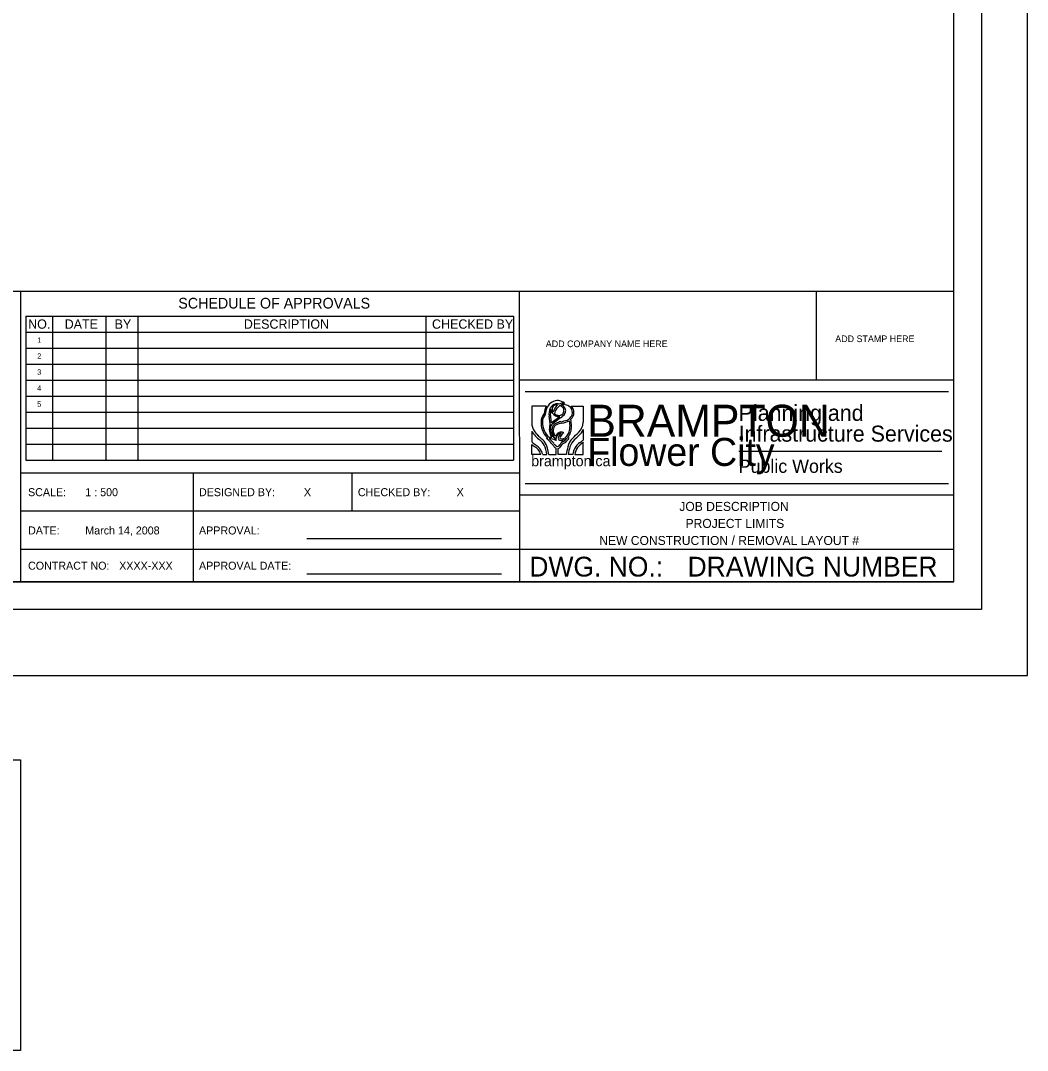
# Model space of a CAD drawing. Extents: x 602909 to 603631, y 4846273 to 4846729.
# Drawn here: x 603194.8 to 603377, y 4846272.8 to 4846459.2 of the extents above; entities that cross this region are included whole.
import ezdxf

# ---------------------------------------------------------------- set-up
doc = ezdxf.new("R2010")
doc.units = 0
for name, color, linetype in [('-PRINT FULLSIZE', 7, 'Continuous'), ('-PRINT HALFSIZE', 7, 'Continuous'), ('ENG_BORDER', 7, 'Continuous'), ('ENG_LOGO', 7, 'Continuous'), ('ENG_TITLEBLOCK', 7, 'Continuous'), ('ENG_TX_LOGO', 7, 'Continuous'), ('ENG_TX_TITLEBLOCK', 7, 'Continuous'), ('ENG_WK_MISC-1', 7, 'Continuous'), ('SL - Border Text', 7, 'Continuous')]:
    doc.layers.add(name, color=color, linetype=linetype)

# ---------------------------------------------------------------- blocks, each defined once
blk = doc.blocks.new('PIS-PW TITLE-H')
at = {"layer": 'ENG_LOGO'}
for p, q in [((-75.42, 14.45), (-78.15, 14.45)), ((-78.15, 14.45), (-78.15, 11.26)), ((-70.72, 14.45), (-68.47, 14.45)), ((-68.47, 14.45), (-68.47, 11.45)), ((-74.69, 11.23), (-74.85, 12.58)), ((-74.43, 11.34), (-74.65, 13.06)), ((-72.89, 12.5), (-74.43, 11.34)), ((-72.76, 12.26), (-74.31, 11.1)), ((-78.15, 9.79), (-78.15, 7.81)), ((-68.47, 10.08), (-68.47, 8.17)), ((-74.92, 8.64), (-74.39, 8.64)), ((-73.76, 8.31), (-73.76, 8.45)), ((-72.07, 7.93), (-71.51, 8.46)), ((-78.15, 5.39), (-78.15, 7.29)), ((-73.55, 5.39), (-73.55, 6.62)), ((-73.17, 5.39), (-73.17, 6.56)), ((-68.47, 5.39), (-68.47, 7.65)), ((-76.45, 5.39), (-78.15, 5.39)), ((-76.06, 5.39), (-75.33, 5.39)), ((-74.96, 5.39), (-73.55, 5.39)), ((-71.67, 5.39), (-73.17, 5.39)), ((-70.41, 5.39), (-71.29, 5.39)), ((-70.05, 5.39), (-68.47, 5.39))]:
    blk.add_line(p, q, dxfattribs=at)
for centre, major_axis, start_param, end_param in [((-73.32, 12.77), (0, 2.75), 5.678233, 7.807497), ((-73.93, 13.08), (0, 2.24), 0.915828, 1.568717), ((-73.37, 13.09), (0, -1.84), 3.318986, 4.976585), ((-73.42, 13.22), (0, 1.47), 1.119551, 1.674398), ((-73.07, 13.94), (0, -1.75), 4.758696, 4.974719), ((-73.69, 13.89), (0, 0.753), 1.423327, 2.376918), ((-73.81, 14), (0, 0.606), 0.666047, 1.576027), ((-72, 12.52), (0, 2.67), 0.628774, 1.255965), ((-73.5, 13.33), (0, 1.36), 6.118882, 6.855525), ((-71.91, 12.4), (0, 2.47), 0.484278, 1.276713), ((-73.45, 13.49), (0, 1.43), 5.937042, 6.443816), ((-72.17, 12.32), (0, 2.72), 6.209925, 6.677582), ((-73.16, 13.3), (0, 1.33), 5.514665, 6.02559), ((-72.16, 12.72), (0, 2.07), 6.104016, 6.552384), ((-72.88, 13.34), (0, 1.4), 5.100192, 6.058655), ((-72.72, 13.61), (0, 0.767), 4.934552, 5.720905), ((-72.91, 13.71), (0, -0.969), 0.785512, 1.640949), ((-72.69, 13.68), (0, 1.09), 4.195874, 4.894963), ((-72.33, 11.8), (0, 3), 5.705811, 6.088794), ((-71.57, 13.27), (0, 1.28), 4.747453, 5.681752), ((-71.24, 13.43), (0, 1.19), 4.858966, 5.733736), ((-72.43, 13.38), (0, -2.61), 1.316711, 1.656268), ((-74.49, 11.45), (0, 2.27), 0.764321, 1.571722), ((-74.55, 11.5), (0, 1.9), 0.74139, 1.563754), ((-75.01, 12.56), (0, -0.186), 1.717889, 1.834992), ((-73.96, 13.66), (0, -0.65), 4.989814, 5.515803), ((-73, 14.66), (0, -2.16), 5.455385, 6.346676), ((-73.1, 14.2), (0, -1.44), 5.558935, 6.198642), ((-73, 14.01), (0, -1.26), 6.098575, 6.969537), ((-73.81, 14.79), (0, -2.82), 0.460861, 0.945922), ((-74.45, 24.58), (0, -13.19), 0.161819, 0.267812), ((-74.01, 21.47), (0, -10.34), 0.177455, 0.344982), ((-72.14, 13.9), (0, -2.16), 0.344201, 0.831804), ((-73.76, 10.77), (0, 3.34), 4.273394, 5.005808), ((-72.01, 13.79), (0, -2.29), 0.654188, 1.084874), ((-74.63, 10.73), (0, -4.7), 1.565289, 1.83996), ((-71.33, 13.22), (0, 0.997), 3.823835, 4.807307), ((-76.01, 11.44), (0, -2.56), 4.785712, 5.370532), ((-75.36, 11.97), (0, -3.98), 5.292666, 5.605077), ((-73.65, 13.61), (0, -6.12), 5.369755, 5.566262), ((-74.17, 11.24), (0, 2.66), 1.493845, 2.002346), ((-73.58, 11.27), (0, -3.33), 5.06368, 5.674398), ((-73.24, 11.46), (0, 3.46), 1.555738, 2.522651), ((-72.88, 10.15), (0, 2.35), 1.184297, 2.265825), ((-74.99, 11.18), (0, 0.371), 4.32589, 4.859481), ((-72.5, 10.29), (0, -2.55), 4.68622, 4.981796), ((-73.83, 10.33), (0, 0.964), 0.63706, 1.540523), ((-72.74, 10.03), (0, 1.93), 1.258524, 1.853874), ((-73.29, 9.91), (0, 1.38), 0.28455, 1.028854), ((-73.1, 9.94), (0, 1.21), 1.326911, 2.090694), ((-73.34, 10.1), (0, 0.888), 0.179588, 1.425103), ((-72.62, 8.16), (0, 1.44), 5.87892, 7.368381), ((-71.39, 4.29), (0, 7.44), 0.207106, 0.364997), ((-71.81, 5.89), (0, 5.46), 0.147367, 0.372097), ((-72.98, 10.56), (0, -2.73), 0.78097, 1.623824), ((-71.01, 11.91), (0, -3.07), 0.712478, 1.421371), ((-71.69, 12.5), (0, -4.55), 0.682687, 1.010528), ((-73.45, 15.04), (0, -9.15), 5.623762, 5.757196), ((-74.17, 13.11), (0, -5.77), 5.537119, 5.75381), ((-11.92, 112.2), (0, -129.21), 5.63745, 5.644913), ((-78.53, 4.94), (0, 3.93), 5.320654, 5.659535), ((-77.29, 6.41), (0, 2.29), 5.416876, 5.78378), ((-77.88, 5.61), (0, 3.35), 5.018027, 5.462353), ((-74.77, 7.29), (0, 1.34), 0.365522, 0.597805), ((-77.01, 4.73), (0, 4.14), 5.439641, 5.800947), ((-74.75, 5.22), (0, 3.14), 5.823202, 6.334077), ((-77.76, 3.17), (0, 6.23), 5.482733, 5.697338), ((-72.53, 10.38), (0, -2.54), 5.019488, 5.665896), ((-72.42, 10.14), (0, -2.33), 4.995413, 5.526463), ((-72.63, 10.06), (0, -1.76), 5.131028, 5.477302), ((-72.6, 8.21), (0, -1.19), 3.173377, 4.865507), ((-72.84, 8.49), (0, 0.39), 1.287529, 2.899642), ((-72.16, 8.3), (0, 1.23), 0.477744, 1.324571), ((-72.57, 9.14), (0, -1.11), 5.896411, 6.466099), ((-72.62, 8.59), (0, 0.276), 0.693494, 2.795441), ((-71.13, 7.42), (0, 2.4), 0.532188, 0.957727), ((-72.28, 7.12), (0, 0.637), 0.214109, 1.153309), ((-72.57, 10.32), (0, -2), 6.206413, 6.519617), ((-73.45, 12.88), (0, -4.98), 0.25264, 0.48256), ((-73.31, 10.42), (0, -2.89), 0.390063, 0.537232), ((-73.45, 10.87), (0, -3.72), 0.408149, 0.566756), ((-72.98, 10.64), (0, -2.45), 0.401305, 1.020747), ((-74.54, 11.95), (0, -5.35), 0.664019, 0.865631), ((-71.66, 7.54), (0, 1.13), 5.695616, 5.978543), ((-69.07, 6.19), (0, 2.82), 0.6523, 1.336939), ((-68.18, 5.39), (0, 3.66), 0.690534, 1.157714), ((-96.81, 48.11), (0, -50.61), 0.669806, 0.705808), ((-82.82, 29.47), (0, -26.1), 0.619451, 0.667551), ((-75.9, 20.01), (0, -14.8), 0.573803, 0.643743), ((-74.61, 13.52), (0, -7.52), 5.687848, 5.809574), ((-78.43, 4.59), (0, 2.5), 5.497917, 5.817483), ((-79.56, 2.67), (0, 5.21), 5.540505, 5.738863), ((-78.51, 4.55), (0, 2.6), 5.039091, 5.480629), ((-78.45, 4.47), (0, 3), 5.021624, 5.458474), ((-78.36, 5.18), (0, 3.62), 4.76812, 5.296774), ((-78.91, 4.92), (0, 4.75), 4.811691, 5.079969), ((-85.55, -5.35), (0, 18.48), 5.441321, 5.480214), ((-72.71, 8.74), (0, -2), 5.382989, 5.704264), ((-73.35, 7.64), (0, -1.05), 5.423199, 6.055208), ((-73.3, 7.54), (0, -0.612), 5.581796, 6.941571), ((-73.56, 7.96), (0, -1.47), 0.32402, 1.048968), ((-75.34, 9.63), (0, -3.81), 0.828888, 0.938456), ((-71.86, 6.52), (0, 1.03), 0.422403, 0.821661), ((-65.77, 4.42), (0, 7.11), 1.223572, 1.434629), ((-61.41, 3.3), (0, 11.98), 1.268607, 1.395258), ((-68.35, 5.26), (0, 2.47), 0.824174, 1.519908), ((-67.53, 4.86), (0, 3.06), 0.923116, 1.39853), ((-68.28, 5.34), (0, 2.48), 0.445246, 0.869293), ((-67.08, 3.92), (0, 4.08), 0.417687, 0.818457)]:
    blk.add_ellipse(centre, major_axis=major_axis, ratio=0.837209, start_param=start_param, end_param=end_param, dxfattribs=at)
at = {"layer": 'ENG_TITLEBLOCK'}
for p, q in [((-79.4, 17.2), (0, 17.2)), ((-39.34, 6.03), (-1.27, 6.04)), ((-79.4, 0), (0, 0))]:
    blk.add_line(p, q, dxfattribs=at)
at = {"layer": 'ENG_TX_LOGO'}
blk.add_text('brampton.ca', height=2, rotation=0.002, dxfattribs=at).set_placement((-78.24, 3.21))
at = {"layer": 'ENG_TX_TITLEBLOCK'}
for s, height, p in [('BRAMPTON', 6, (-67.72, 8.74)), ('Planning and', 3, (-39.34, 11.71)), ('Infrastructure Services', 3, (-39.34, 7.82)), ('Flower City', 5.25, (-67.72, 3.27)), ('Public Works', 2.5, (-39.34, 1.97))]:
    blk.add_text(s, height=height, rotation=0.0021, dxfattribs=at).set_placement(p)

msp = doc.modelspace()

# ---------------------------------------------------------------- linework, layer by layer
at = {"layer": '-PRINT FULLSIZE'}
msp.add_lwpolyline([(602930, 4846340.65), (603377.03, 4846340.65), (603377.03, 4846645.65), (602930, 4846645.65)], close=True, dxfattribs=at)
at = {"layer": '-PRINT HALFSIZE'}
msp.add_lwpolyline([(602959.8, 4846631.64), (603368.72, 4846631.64), (603368.72, 4846352.64), (602959.8, 4846352.64)], close=True, dxfattribs=at)
at = {"layer": 'ENG_BORDER'}
for p, q in [((603363.72, 4846357.64), (603363.72, 4846626.85)), ((602977.52, 4846410.23), (603363.74, 4846410.23)), ((603194.76, 4846410.25), (603194.76, 4846357.64)), ((603285.12, 4846357.64), (603285.08, 4846410.25)), ((603338.86, 4846394.19), (603338.86, 4846410.23)), ((603285.09, 4846394.19), (603363.72, 4846394.19)), ((603285.11, 4846377.32), (603194.76, 4846377.32)), ((603226.09, 4846357.72), (603226.09, 4846377.32)), ((603254.8, 4846370.39), (603254.8, 4846377.32)), ((603285.23, 4846373.35), (603363.75, 4846373.35)), ((603285.14, 4846370.39), (603194.76, 4846370.39)), ((603363.66, 4846363.45), (603194.76, 4846363.45)), ((603363.72, 4846357.64), (602977.52, 4846357.64))]:
    msp.add_line(p, q, dxfattribs=at)
for points in [[(602977.52, 4846357.64), (603363.72, 4846357.64), (603363.72, 4846626.64), (602977.52, 4846626.64)], [(603054.8, 4846325.39), (603194.76, 4846325.39), (603194.76, 4846272.8), (603054.8, 4846272.8)]]:
    msp.add_lwpolyline(points, close=True, dxfattribs=at)
at = {"layer": 'ENG_TX_TITLEBLOCK'}
for points in [[(603246.57, 4846365.47), (603281.85, 4846365.47)], [(603246.57, 4846359.1), (603281.85, 4846359.1)]]:
    msp.add_lwpolyline(points, dxfattribs=at)
at = {"layer": 'SL - Border Text'}
for p, q in [((603195.73, 4846405.73), (603195.73, 4846379.66)), ((603195.73, 4846405.73), (603284.02, 4846405.73)), ((603200.56, 4846405.73), (603200.56, 4846379.66)), ((603210.21, 4846405.73), (603210.21, 4846379.66)), ((603216, 4846405.73), (603216, 4846379.66)), ((603268.14, 4846405.73), (603268.14, 4846379.66)), ((603284.02, 4846405.73), (603284.02, 4846379.66)), ((603195.73, 4846402.84), (603284.02, 4846402.84)), ((603195.73, 4846399.94), (603284.02, 4846399.94)), ((603195.73, 4846397.04), (603284.02, 4846397.04)), ((603195.73, 4846394.15), (603284.02, 4846394.15)), ((603195.73, 4846391.25), (603284.02, 4846391.25)), ((603195.73, 4846388.35), (603284.02, 4846388.35)), ((603195.73, 4846385.46), (603284.02, 4846385.46)), ((603195.73, 4846382.56), (603284.02, 4846382.56)), ((603195.73, 4846379.66), (603284.02, 4846379.66))]:
    msp.add_line(p, q, dxfattribs=at)

# ---------------------------------------------------------------- block references
at = {"layer": 'ENG_WK_MISC-1', "xscale": 0.9654884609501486, "yscale": 0.9654884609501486}
msp.add_blockref('PIS-PW TITLE-H', (603362.74, 4846375.45), dxfattribs=at)

# ---------------------------------------------------------------- texts
at = {"layer": 'ENG_TX_TITLEBLOCK'}
for s, height, rotation, p in [('SCHEDULE OF APPROVALS', 1.931, 360, (603223.31, 4846407.1)), ('NO.', 1.69, 360, (603196.13, 4846403.44)), ('DATE', 1.69, 360, (603202.74, 4846403.44)), ('BY', 1.69, 360, (603211.78, 4846403.44)), ('DESCRIPTION', 1.6896, 360, (603235.17, 4846403.44)), ('CHECKED BY', 1.69, 360, (603269.24, 4846403.44)), ('1', 0.965, 359.9999, (603197.77, 4846400.9)), ('ADD COMPANY NAME HERE', 1.2069, 360, (603289.84, 4846400.11)), ('ADD STAMP HERE', 1.2069, 360, (603342.24, 4846401.02)), ('2', 0.965, 359.9999, (603197.77, 4846398.01)), ('3', 0.965, 359.9999, (603197.77, 4846395.11)), ('4', 0.965, 359.9999, (603197.77, 4846392.22)), ('5', 0.965, 359.9999, (603197.77, 4846389.32)), ('1 : 500', 1.448, 360, (603206.47, 4846373.13)), ('DESIGNED BY:', 1.4482, 360, (603227.06, 4846373.13)), ('X', 1.45, 360, (603246.05, 4846373.13)), ('CHECKED BY:', 1.4482, 360, (603255.82, 4846373.13)), ('X', 1.45, 360, (603273.7, 4846373.13)), ('JOB DESCRIPTION', 1.6356, 360, (603314.01, 4846370.46)), ('March 14, 2008', 1.4482, 360, (603206.47, 4846366.2)), ('PROJECT LIMITS', 1.6356, 360, (603315.14, 4846367.38)), ('APPROVAL:', 1.448, 360, (603227.06, 4846366.2)), ('NEW CONSTRUCTION / REMOVAL LAYOUT #', 1.6356, 360, (603299.52, 4846364.29)), ('DWG. NO.:', 3.583, 360, (603286.86, 4846358.58)), ('DRAWING NUMBER', 3.583, 360, (603315.5, 4846358.58)), ('CONTRACT NO:', 1.4482, 360, (603196.11, 4846359.82)), ('XXXX-XXX', 1.448, 360, (603212.61, 4846359.82)), ('APPROVAL DATE:', 1.4482, 360, (603227.06, 4846359.82))]:
    msp.add_text(s, height=height, rotation=rotation, dxfattribs=at).set_placement(p)
for s, p in [('SCALE:', (603196.11, 4846373.13)), ('DATE:', (603196.11, 4846366.2))]:
    msp.add_text(s, height=1.448, dxfattribs=at).set_placement(p)

doc.saveas('drawing.dxf')
